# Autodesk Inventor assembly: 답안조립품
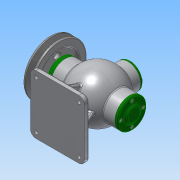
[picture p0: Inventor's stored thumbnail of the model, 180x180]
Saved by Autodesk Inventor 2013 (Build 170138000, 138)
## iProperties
Created: 2018-06
Part Number: 답안조립품
Document SubType Name: Assembly
Designer: Administrator
Author: Administrator
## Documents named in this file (19)
- C:\Users\Administrator\Desktop\480612V1004\답안조립품.iam
- C:\Users\Administrator\Desktop\480612V1004\본체.ipt
- C:\Users\Administrator\Desktop\480612V1004\V-벨트풀리.ipt
- C:\Users\Administrator\Desktop\480612V1004\너트 M8.ipt
- C:\Users\Administrator\Desktop\480612V1004\뒤커버.ipt
- C:\Users\Administrator\Desktop\480612V1004\멈춤링 15x1.ipt
- C:\Users\Administrator\Desktop\480612V1004\멈춤링 35x1.6.ipt
- 멈춤링 35x1.6.ipt
- C:\Users\Administrator\Desktop\480612V1004\베어링 6202.ipt
- 베어링 6202.ipt
- C:\Users\Administrator\Desktop\480612V1004\볼트 M4x12.ipt
- C:\Users\Administrator\Desktop\480612V1004\볼트 M4x16.ipt
- C:\Users\Administrator\Desktop\480612V1004\부시.ipt
- C:\Users\Administrator\Desktop\480612V1004\상부커버.ipt
- C:\Users\Administrator\Desktop\480612V1004\슬라이드.ipt
- C:\Users\Administrator\Desktop\480612V1004\앞커버.ipt
- C:\Users\Administrator\Desktop\480612V1004\오일 실 15 30 7.ipt
- C:\Users\Administrator\Desktop\480612V1004\키 4x4x12.ipt
- C:\Users\Administrator\Desktop\480612V1004\편심축.ipt
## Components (1 placed, 1 different names)
1. V-벨트풀리:1 — 각도:1
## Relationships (1: Angle 1)
- 각도:1 [Angle]: V-벨트풀리:1
